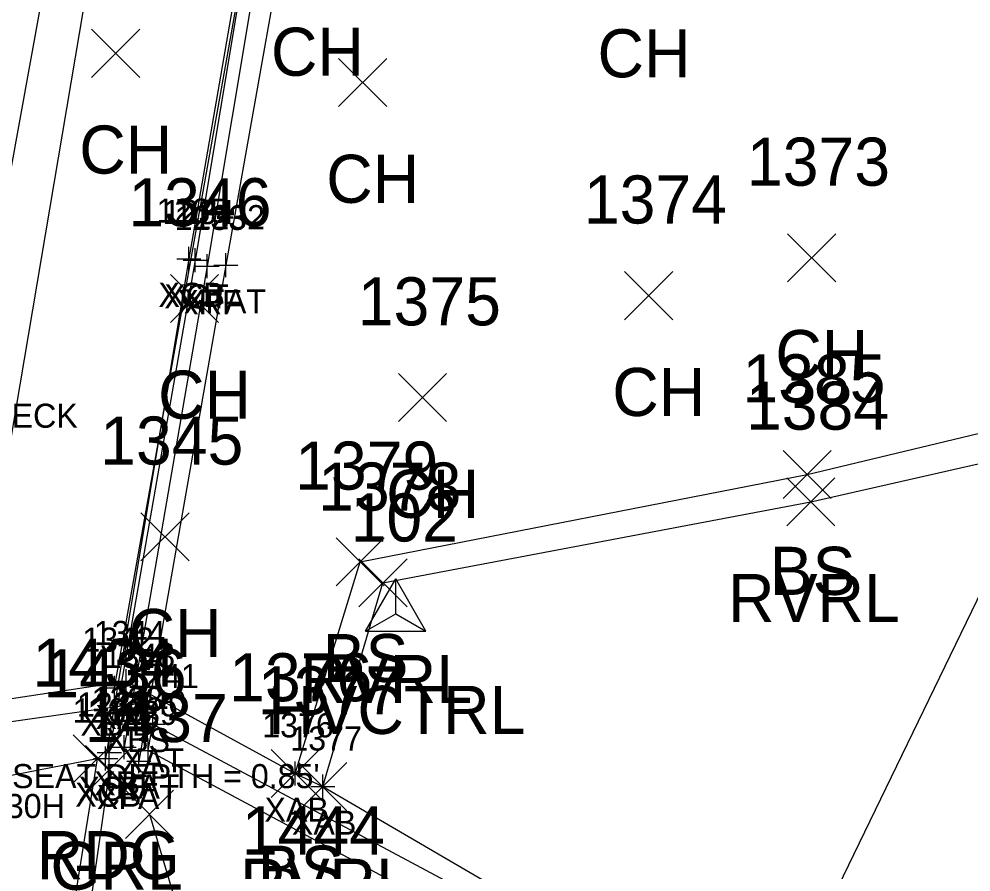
# Model space of a CAD drawing. Extents: x 1678553 to 1680768, y 787260 to 792325.
# Drawn here: x 1678697.83 to 1678737.39, y 787518.76 to 787554.21 of the extents above; entities that cross this region are included whole.
import ezdxf

# ---------------------------------------------------------------- set-up
doc = ezdxf.new("R2010")
doc.units = 0
for name, color, linetype in [('B_A', 7, 'Continuous'), ('B_C', 7, 'Continuous'), ('B_I', 7, 'Continuous'), ('B_TIC', 7, 'Continuous'), ('BB', 7, 'Continuous'), ('BDC', 7, 'Continuous'), ('BELB', 7, 'Continuous'), ('BF', 7, 'Continuous'), ('BR', 7, 'Continuous'), ('BSE', 7, 'Continuous'), ('BSUBM', 7, 'Continuous'), ('C_A', 7, 'Continuous'), ('C_I', 7, 'Continuous'), ('CPSM', 7, 'Continuous'), ('L_A', 7, 'Continuous'), ('L_I', 7, 'Continuous'), ('L_TIC', 7, 'Continuous'), ('LAWE', 7, 'Continuous'), ('LELB', 7, 'Continuous'), ('P_A', 7, 'Continuous'), ('P_I', 7, 'Continuous'), ('P_TIC', 7, 'Continuous'), ('PEU', 7, 'Continuous'), ('R_A', 7, 'Continuous'), ('R_I', 7, 'Continuous'), ('R_TIC', 7, 'Continuous'), ('RGR', 7, 'Continuous')]:
    doc.layers.add(name, color=color, linetype=linetype)

msp = doc.modelspace()

# ---------------------------------------------------------------- linework, layer by layer
at = {"layer": 'B_TIC'}
for p, q in [((1678704.89, 787544.249), (1678704.966, 787544.249)), ((1678705.149, 787544.189), (1678705.224, 787544.189)), ((1678705.645, 787543.945), (1678705.721, 787543.945)), ((1678706.426, 787543.978), (1678706.501, 787543.978)), ((1678701.807, 787526.419), (1678701.882, 787526.419)), ((1678702.289, 787526.696), (1678702.365, 787526.696)), ((1678702.693, 787525.745), (1678702.768, 787525.745)), ((1678703.392, 787524.9), (1678703.467, 787524.9)), ((1678701.586, 787523.722), (1678701.661, 787523.722)), ((1678702.199, 787523.942), (1678702.275, 787523.942)), ((1678703.196, 787523.813), (1678703.271, 787523.813)), ((1678703.196, 787523.813), (1678703.271, 787523.813)), ((1678701.433, 787523.472), (1678701.509, 787523.472)), ((1678702.809, 787523.371), (1678702.885, 787523.371)), ((1678709.313, 787522.854), (1678709.388, 787522.854)), ((1678710.453, 787522.307), (1678710.529, 787522.307))]:
    msp.add_line(p, q, dxfattribs=at)
for points in [[(1678704.887, 787543.749), (1678704.887, 787544.749)], [(1678705.145, 787543.689), (1678705.145, 787544.689)], [(1678704.387, 787544.249), (1678705.387, 787544.249)], [(1678704.645, 787544.189), (1678705.645, 787544.189)], [(1678705.642, 787543.445), (1678705.642, 787544.445)], [(1678706.422, 787543.478), (1678706.422, 787544.478)], [(1678705.142, 787543.945), (1678706.142, 787543.945)], [(1678705.922, 787543.978), (1678706.922, 787543.978)], [(1678702.286, 787526.196), (1678702.286, 787527.196)], [(1678701.803, 787525.919), (1678701.803, 787526.919)], [(1678701.303, 787526.419), (1678702.303, 787526.419)], [(1678701.786, 787526.696), (1678702.786, 787526.696)], [(1678702.689, 787525.245), (1678702.689, 787526.245)], [(1678702.189, 787525.745), (1678703.189, 787525.745)], [(1678703.388, 787524.4), (1678703.388, 787525.4)], [(1678702.888, 787524.9), (1678703.888, 787524.9)], [(1678702.196, 787523.442), (1678702.196, 787524.442)], [(1678701.582, 787523.222), (1678701.582, 787524.222)], [(1678703.192, 787523.313), (1678703.192, 787524.313)], [(1678703.192, 787523.313), (1678703.192, 787524.313)], [(1678701.082, 787523.722), (1678702.082, 787523.722)], [(1678701.43, 787522.972), (1678701.43, 787523.972)], [(1678701.696, 787523.942), (1678702.696, 787523.942)], [(1678702.692, 787523.813), (1678703.692, 787523.813)], [(1678702.692, 787523.813), (1678703.692, 787523.813)], [(1678702.806, 787522.871), (1678702.806, 787523.871)], [(1678700.93, 787523.472), (1678701.93, 787523.472)], [(1678702.306, 787523.371), (1678703.306, 787523.371)], [(1678709.309, 787522.354), (1678709.309, 787523.354)], [(1678708.809, 787522.854), (1678709.809, 787522.854)], [(1678710.45, 787521.807), (1678710.45, 787522.807)], [(1678709.95, 787522.307), (1678710.95, 787522.307)]]:
    msp.add_lwpolyline(points, dxfattribs=at)
at = {"layer": 'BB'}
for points in [[(1678701.803, 787526.419), (1678707.932, 787560.782)], [(1678695.571, 787525.394), (1678701.411, 787559.95)]]:
    msp.add_lwpolyline(points, dxfattribs=at)
at = {"layer": 'BDC'}
for points in [[(1678708.123, 787562.968), (1678704.887, 787544.249), (1678701.43, 787523.472)], [(1678708.282, 787562.971), (1678705.145, 787544.189), (1678701.582, 787523.722)]]:
    msp.add_lwpolyline(points, dxfattribs=at)
at = {"layer": 'BELB'}
msp.add_lwpolyline([(1678692.969, 787524.163), (1678696.171, 787540.725), (1678699.562, 787559.385)], dxfattribs=at)
at = {"layer": 'BF'}
msp.add_lwpolyline([(1678709.743, 787562.716), (1678706.422, 787543.978), (1678702.806, 787523.371)], dxfattribs=at)
at = {"layer": 'BR'}
msp.add_lwpolyline([(1678708.76, 787562.617), (1678705.642, 787543.945), (1678702.196, 787523.942)], dxfattribs=at)
at = {"layer": 'BSE'}
msp.add_lwpolyline([(1678682.999, 787522.966), (1678702.689, 787525.745)], dxfattribs=at)
at = {"layer": 'BSUBM'}
for points in [[(1678669.621, 787510.644), (1678682.749, 787523.742), (1678702.286, 787526.696), (1678709.309, 787522.854), (1678710.45, 787522.307), (1678722.702, 787515.164), (1678722.009, 787513.547)], [(1678703.192, 787523.813), (1678703.388, 787524.9), (1678720.308, 787515.858), (1678719.755, 787514.931)], [(1678703.192, 787523.813), (1678719.755, 787514.931)]]:
    msp.add_lwpolyline(points, dxfattribs=at)
at = {"layer": 'CPSM'}
for p, q in [((1678712.232, 787528.775), (1678713.482, 787530.94)), ((1678714.732, 787528.775), (1678713.482, 787530.94)), ((1678713.482, 787529.496), (1678713.482, 787530.94)), ((1678712.232, 787528.775), (1678713.482, 787529.496)), ((1678713.482, 787529.496), (1678713.482, 787529.496)), ((1678713.482, 787529.496), (1678714.732, 787528.775)), ((1678712.232, 787528.775), (1678714.732, 787528.775))]:
    msp.add_line(p, q, dxfattribs=at)
at = {"layer": 'L_TIC'}
for points in [[(1678700.845, 787551.786), (1678702.845, 787553.786)], [(1678702.845, 787551.786), (1678700.845, 787553.786)], [(1678711.107, 787550.571), (1678713.107, 787552.571)], [(1678713.107, 787550.571), (1678711.107, 787552.571)], [(1678729.768, 787543.285), (1678731.768, 787545.285)], [(1678731.768, 787543.285), (1678729.768, 787545.285)], [(1678704.121, 787541.598), (1678706.121, 787543.598)], [(1678706.121, 787541.598), (1678704.121, 787543.598)], [(1678722.992, 787541.712), (1678724.992, 787543.712)], [(1678724.992, 787541.712), (1678722.992, 787543.712)], [(1678713.597, 787537.479), (1678715.597, 787539.479)], [(1678715.597, 787537.479), (1678713.597, 787539.479)], [(1678729.579, 787534.277), (1678731.579, 787536.277)], [(1678731.579, 787534.277), (1678729.579, 787536.277)], [(1678729.728, 787533.144), (1678731.728, 787535.144)], [(1678731.728, 787533.144), (1678729.728, 787535.144)], [(1678702.895, 787531.691), (1678704.895, 787533.691)], [(1678704.895, 787531.691), (1678702.895, 787533.691)], [(1678711.002, 787530.651), (1678713.002, 787532.651)], [(1678713.002, 787530.651), (1678711.002, 787532.651)], [(1678711.953, 787529.779), (1678713.953, 787531.779)], [(1678713.953, 787529.779), (1678711.953, 787531.779)], [(1678708.309, 787521.854), (1678710.309, 787523.854)], [(1678710.309, 787521.854), (1678708.309, 787523.854)], [(1678709.45, 787521.307), (1678711.45, 787523.307)], [(1678711.45, 787521.307), (1678709.45, 787523.307)], [(1678702.248, 787520.158), (1678704.248, 787522.158)], [(1678704.248, 787520.158), (1678702.248, 787522.158)]]:
    msp.add_lwpolyline(points, dxfattribs=at)
at = {"layer": 'LAWE'}
msp.add_lwpolyline([(1678710.45, 787522.307), (1678712.953, 787530.779), (1678730.728, 787534.144), (1678747.988, 787538.071), (1678754.108, 787543.669), (1678765.435, 787536.978), (1678782.179, 787542.809), (1678814.557, 787545.735)], dxfattribs=at)
at = {"layer": 'LELB'}
for points in [[(1678709.309, 787522.854), (1678712.002, 787531.651), (1678730.579, 787535.277), (1678747.5, 787539.345), (1678753.68, 787544.425), (1678764.209, 787540.735), (1678783.127, 787545.834), (1678814.196, 787552.622)], [(1678740.071, 787535.07), (1678729.409, 787513.098), (1678730.574, 787499.544), (1678734.556, 787489.379)], [(1678703.248, 787521.158), (1678708.077, 787504.893), (1678710.048, 787496.734), (1678699.74, 787468.921), (1678698.818, 787457.487), (1678706.749, 787433.933), (1678714.451, 787417.51), (1678705.647, 787404.222), (1678696.305, 787404.911), (1678687.529, 787400.609), (1678678.856, 787394.601), (1678669.013, 787365.188), (1678664.736, 787349.076), (1678657.46, 787321.279), (1678652.337, 787297.827), (1678647.466, 787276.322)]]:
    msp.add_lwpolyline(points, dxfattribs=at)
at = {"layer": 'P_TIC'}
for points in [[(1678700.084, 787522.46), (1678702.084, 787524.46)], [(1678702.084, 787522.46), (1678700.084, 787524.46)], [(1678700.084, 787522.46), (1678702.084, 787524.46)], [(1678702.084, 787522.46), (1678700.084, 787524.46)]]:
    msp.add_lwpolyline(points, dxfattribs=at)
at = {"layer": 'PEU'}
for points in [[(1678701.084, 787523.46), (1678691.863, 787521.675), (1678683.928, 787520.501), (1678679.423, 787498.085), (1678675.858, 787484.768), (1678672.353, 787466.03), (1678666.651, 787446.983), (1678662.975, 787430.653), (1678658.139, 787412.595), (1678657.115, 787400.242), (1678651.997, 787380.889), (1678646.796, 787355.993), (1678640.868, 787332.433), (1678631.508, 787300.964), (1678626.743, 787281.591)], [(1678701.084, 787523.46), (1678699.331, 787512.572), (1678697.82, 787495.037), (1678694.118, 787469.827), (1678689.971, 787450.935), (1678685.799, 787426.952), (1678675.551, 787395.19), (1678665.556, 787365.837), (1678662.398, 787349.046), (1678655.839, 787321.611), (1678650.229, 787298.04), (1678645.331, 787276.771)]]:
    msp.add_lwpolyline(points, dxfattribs=at)
at = {"layer": 'R_TIC'}
for points in [[(1678700.594, 787522.02), (1678702.594, 787524.02)], [(1678702.594, 787522.02), (1678700.594, 787524.02)]]:
    msp.add_lwpolyline(points, dxfattribs=at)
at = {"layer": 'RGR'}
msp.add_lwpolyline([(1678701.594, 787523.02), (1678700.119, 787512.729), (1678700.258, 787508.965), (1678701.723, 787505.648), (1678704.495, 787501.711)], dxfattribs=at)

# ---------------------------------------------------------------- texts
at = {"layer": 'B_A'}
for s, p in [('XCB', (1678703.623, 787542.249)), ('XCT', (1678703.866, 787542.189)), ('XRF', (1678704.402, 787541.945)), ('XFAT', (1678704.678, 787541.978)), ('XAB', (1678701.006, 787524.696)), ('XBIB', (1678700.374, 787524.419)), ('XBS', (1678701.429, 787523.745)), ('XAT', (1678702.093, 787522.9)), ('XRF', (1678700.956, 787521.942)), ('XCB', (1678700.166, 787521.472)), ('XCT', (1678700.303, 787521.722)), ('XAT', (1678701.897, 787521.813)), ('XAT', (1678701.897, 787521.813)), ('XFAT', (1678701.062, 787521.371)), ('XAB', (1678708.03, 787520.854)), ('XAB', (1678709.17, 787520.307))]:
    msp.add_text(s, height=1, dxfattribs=at).set_placement(p)
at = {"layer": 'B_C'}
for s, p in [('PAVED DECK', (1678691.652, 787537.225)), ("BRIDGE SEAT DEPTH = 0.85'", (1678692.044, 787522.245)), ('BEAM DIMENSIONS 0.78W X 2.30H', (1678677.663, 787521.001))]:
    msp.add_text(s, height=1, dxfattribs=at).set_placement(p)
at = {"layer": 'B_I'}
for s, p in [('1235', (1678703.54, 787545.749)), ('1234', (1678703.799, 787545.689)), ('1233', (1678704.295, 787545.445)), ('1232', (1678705.076, 787545.478)), ('1344', (1678700.939, 787528.196)), ('1342', (1678700.457, 787527.919)), ('1343', (1678701.343, 787527.245)), ('1241', (1678702.325, 787526.4)), ('1238', (1678700.85, 787525.442)), ('1237', (1678700.236, 787525.222)), ('1240', (1678701.802, 787525.313)), ('1240', (1678701.802, 787525.313)), ('1236', (1678700.056, 787524.972)), ('1239', (1678701.456, 787524.871)), ('1376', (1678707.935, 787524.354)), ('1377', (1678709.103, 787523.807))]:
    msp.add_text(s, height=1, dxfattribs=at).set_placement(p)
at = {"layer": 'C_A'}
msp.add_text('HVCTRL', height=2, dxfattribs=at).set_placement((1678708.175, 787524.496))
at = {"layer": 'C_I'}
msp.add_text('102', height=2, dxfattribs=at).set_placement((1678711.608, 787532.496))
at = {"layer": 'L_A'}
for s, p in [('CH', (1678708.299, 787551.853)), ('CH', (1678721.868, 787551.79)), ('CH', (1678700.333, 787547.786)), ('CH', (1678710.595, 787546.571)), ('CH', (1678729.256, 787539.285)), ('CH', (1678703.609, 787537.598)), ('CH', (1678722.481, 787537.712)), ('CH', (1678713.086, 787533.479)), ('BS', (1678729.02, 787530.277)), ('RVRL', (1678727.295, 787529.144)), ('CH', (1678702.383, 787527.691)), ('BS', (1678710.443, 787526.651)), ('RVRL', (1678709.52, 787525.779)), ('BS', (1678707.75, 787517.854)), ('RVRL', (1678707.017, 787517.307))]:
    msp.add_text(s, height=2, dxfattribs=at).set_placement(p)
at = {"layer": 'L_I'}
for s, p in [('1373', (1678728.075, 787547.285)), ('1346', (1678702.373, 787545.598)), ('1374', (1678721.3, 787545.712)), ('1375', (1678711.905, 787541.479)), ('1385', (1678727.886, 787538.277)), ('1384', (1678728.035, 787537.144)), ('1345', (1678701.202, 787535.691)), ('1379', (1678709.302, 787534.651)), ('1378', (1678710.26, 787533.779)), ('1376', (1678706.561, 787525.854)), ('1377', (1678707.757, 787525.307)), ('1437', (1678700.556, 787524.158)), ('1444', (1678707.09, 787519.485))]:
    msp.add_text(s, height=2, dxfattribs=at).set_placement(p)
at = {"layer": 'P_A'}
msp.add_text('RDG', height=2, dxfattribs=at).set_placement((1678698.572, 787518.46))
msp.add_text('RDG', height=2, dxfattribs=at).set_placement((1678698.572, 787518.46))
at = {"layer": 'P_I'}
msp.add_text('1434', height=2, dxfattribs=at).set_placement((1678698.391, 787526.46))
msp.add_text('1434', height=2, dxfattribs=at).set_placement((1678698.391, 787526.46))
at = {"layer": 'R_A'}
msp.add_text('GRL', height=2, dxfattribs=at).set_placement((1678699.137, 787518.02))
at = {"layer": 'R_I'}
msp.add_text('1436', height=2, dxfattribs=at).set_placement((1678698.846, 787526.02))

doc.saveas('drawing.dxf')
